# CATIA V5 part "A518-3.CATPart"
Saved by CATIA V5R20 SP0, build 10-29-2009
Part number: A518-3
Source: Unknown
Property "ARTICLENO": "A518-3"
Property "BOMINFO": "A518-3"
Property "CODE": "A518-3"
Property "D": "50.000"
Property "H": "40.000"
Property "H1": "63.000"
Property "L": "80.000"
Property "L1": "60.000"
Property "LINA": "A518-3"
Property "NB": "A518-3"
Property "NBSYN": "$CODE."
Property "NN": "A518"
Property "NT": "Shock Absorber for Pad Retainer Pins"
Property "PINDIA": "50.000"
Property "R": "23.000"
Property "SUPPLIER": "CF"
Bounding box of the stored display mesh (mm): x -25 to 20.263, y 0 to 80, z -24.989 to 24.989
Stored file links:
  C:\Users\Utente\Desktop\3D files A518\A518-3.CATPart
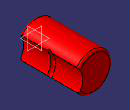
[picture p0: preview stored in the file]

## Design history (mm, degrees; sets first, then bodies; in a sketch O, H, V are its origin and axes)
Body1 "Geometry.1" (main body)
  Solid1 "A518-3.catpart": solid without history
